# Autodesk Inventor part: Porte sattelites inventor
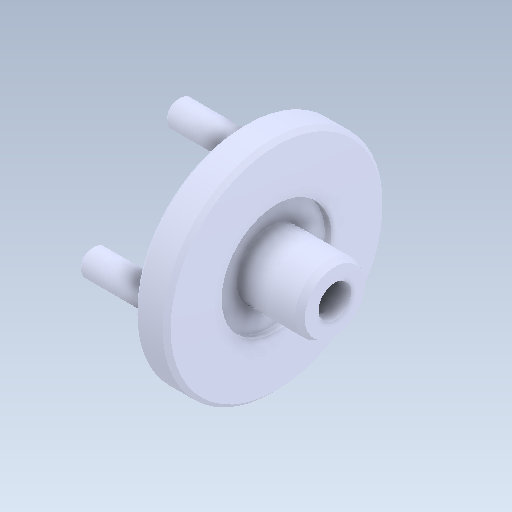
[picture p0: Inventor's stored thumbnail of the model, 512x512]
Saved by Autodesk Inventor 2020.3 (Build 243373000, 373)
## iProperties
Created: 2019-01
Part Number: Porte sattelites inventor
Material: Générique
Document SubType Name: Modeling
Designer: ficho
Density: 1 g/cm^3
Appearance: Par défaut
Mass: 0.619253 g
Surface Area: 7.99302 cm^2
Volume: 0.619253 cm^3
Sending System: SolidWorks 2015
Last Author: adrien
Last Saved: 2019-01-11
Author: ficho
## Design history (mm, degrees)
node "Boss.-Extru.3"
sketch "Esquisse1"
  geometry: A1 r 2.909 centre (0.384, 3.431) between (-2.245, 2.184) and (-1.899, 1.627) reference; A2 r 2.5 centre (0, 0) between (-0.96, 2.308) and (-1.899, 1.627) reference; A3 r 2.909 centre (-3.381, 0.695) between (-0.96, 2.308) and (-1.383, 2.81) reference; A4 r 4.512 centre (-3.768, -1.02) between (-1.383, 2.81) and (-2.039, 3.147) reference; A5 r 3.75 centre (0, 0) between (-2.039, 3.147) and (-2.363, 2.912) reference; A6 r 4.512 centre (2.135, 3.268) between (-2.363, 2.912) and (-2.245, 2.184) reference; A7 r 2.909 centre (-1.706, 3.001) between (-3.1, 0.447) and (-2.492, 0.2) reference; A8 r 2.5 centre (0, 0) between (-2.134, 1.303) and (-2.492, 0.2) reference; A9 r 2.909 centre (-3.144, -1.425) between (-2.134, 1.303) and (-2.771, 1.46) reference; A10 r 4.512 centre (-2.448, -3.04) between (-2.771, 1.46) and (-3.5, 1.347) reference; A11 r 3.75 centre (0, 0) between (-3.5, 1.347) and (-3.623, 0.967) reference; A12 r 4.512 centre (-0.194, 3.899) between (-3.623, 0.967) and (-3.1, 0.447) reference; A13 r 2.909 centre (-3.144, 1.425) between (-2.771, -1.46) and (-2.134, -1.303) reference; A14 r 2.5 centre (0, 0) between (-2.492, -0.2) and (-2.134, -1.303) reference; A15 r 2.909 centre (-1.706, -3.001) between (-2.492, -0.2) and (-3.1, -0.447) reference; A16 r 4.512 centre (-0.194, -3.899) between (-3.1, -0.447) and (-3.623, -0.967) reference; A17 r 3.75 centre (0, 0) between (-3.623, -0.967) and (-3.5, -1.347) reference; A18 r 4.512 centre (-2.448, 3.04) between (-3.5, -1.347) and (-2.771, -1.46) reference; A19 r 2.909 centre (-3.381, -0.695) between (-1.383, -2.81) and (-0.96, -2.308) reference; A20 r 2.5 centre (0, 0) between (-1.899, -1.627) and (-0.96, -2.308) reference; A21 r 2.909 centre (0.384, -3.431) between (-1.899, -1.627) and (-2.245, -2.184) reference; A22 r 4.512 centre (2.135, -3.268) between (-2.245, -2.184) and (-2.363, -2.912) reference; A23 r 3.75 centre (0, 0) between (-2.363, -2.912) and (-2.039, -3.147) reference; A24 r 4.512 centre (-3.768, 1.02) between (-2.039, -3.147) and (-1.383, -2.81) reference; A25 r 2.909 centre (-2.327, -2.55) between (0.532, -3.086) and (0.58, -2.432) reference; A26 r 2.5 centre (0, 0) between (-0.58, -2.432) and (0.58, -2.432) reference; A27 r 2.909 centre (2.327, -2.55) between (-0.58, -2.432) and (-0.532, -3.086) reference; A28 r 4.512 centre (3.648, -1.389) between (-0.532, -3.086) and (-0.2, -3.745) reference; A29 r 3.75 centre (0, 0) between (-0.2, -3.745) and (0.2, -3.745) reference; A30 r 4.512 centre (-3.648, -1.389) between (0.2, -3.745) and (0.532, -3.086) reference; A31 r 2.909 centre (-0.384, -3.431) between (2.245, -2.184) and (1.899, -1.627) reference; A32 r 2.5 centre (0, 0) between (0.96, -2.308) and (1.899, -1.627) reference; A33 r 2.909 centre (3.381, -0.695) between (0.96, -2.308) and (1.383, -2.81) reference; A34 r 4.512 centre (3.768, 1.02) between (1.383, -2.81) and (2.039, -3.147) reference; A35 r 3.75 centre (0, 0) between (2.039, -3.147) and (2.363, -2.912) reference; A36 r 4.512 centre (-2.135, -3.268) between (2.363, -2.912) and (2.245, -2.184) reference; A37 r 2.909 centre (1.706, -3.001) between (3.1, -0.447) and (2.492, -0.2) reference; A38 r 2.5 centre (0, 0) between (2.134, -1.303) and (2.492, -0.2) reference; A39 r 2.909 centre (3.144, 1.425) between (2.134, -1.303) and (2.771, -1.46) reference; A40 r 4.512 centre (2.448, 3.04) between (2.771, -1.46) and (3.5, -1.347) reference; A41 r 3.75 centre (0, 0) between (3.5, -1.347) and (3.623, -0.967) reference; A42 r 4.512 centre (0.194, -3.899) between (3.623, -0.967) and (3.1, -0.447) reference; A43 r 2.909 centre (3.144, -1.425) between (2.771, 1.46) and (2.134, 1.303) reference; A44 r 2.5 centre (0, 0) between (2.492, 0.2) and (2.134, 1.303) reference; A45 r 2.909 centre (1.706, 3.001) between (2.492, 0.2) and (3.1, 0.447) reference; A46 r 4.512 centre (0.194, 3.899) between (3.1, 0.447) and (3.623, 0.967) reference; A47 r 3.75 centre (0, 0) between (3.623, 0.967) and (3.5, 1.347) reference; A48 r 4.512 centre (2.448, -3.04) between (3.5, 1.347) and (2.771, 1.46) reference; A49 r 2.909 centre (3.381, 0.695) between (1.383, 2.81) and (0.96, 2.308) reference; A50 r 2.5 centre (0, 0) between (1.899, 1.627) and (0.96, 2.308) reference; A51 r 2.909 centre (-0.384, 3.431) between (1.899, 1.627) and (2.245, 2.184) reference; A52 r 4.512 centre (-2.135, 3.268) between (2.245, 2.184) and (2.363, 2.912) reference; A53 r 3.75 centre (0, 0) between (2.363, 2.912) and (2.039, 3.147) reference; A54 r 4.512 centre (3.768, -1.02) between (2.039, 3.147) and (1.383, 2.81) reference; A55 r 2.909 centre (2.327, 2.55) between (-0.532, 3.086) and (-0.58, 2.432) reference; A56 r 2.5 centre (0, 0) between (0.58, 2.432) and (-0.58, 2.432) reference; A57 r 2.909 centre (-2.327, 2.55) between (0.58, 2.432) and (0.532, 3.086) reference; A58 r 4.512 centre (-3.648, 1.389) between (0.532, 3.086) and (0.2, 3.745) reference; A59 r 3.75 centre (0, 0) between (0.2, 3.745) and (-0.2, 3.745) reference; A60 r 4.512 centre (3.648, 1.389) between (-0.2, 3.745) and (-0.532, 3.086) reference; 1 further point
extrude "Extrusion1" cut sketch "Esquisse1" extent not by distance; stored distance "d0" = 4.9; taper "d1" = 0 deg
sketch "Esquisse2"
  geometry: C1 r 8.3 at (0, 0) reference; C2 r 1 at (0, 0) reference; 1 further point
extrude "Extrusion2" cut sketch "Esquisse2" extent not by distance; stored distance "d2" = 4; taper "d3" = 0 deg
sketch "Esquisse3"
  geometry: C1 r 1 at (0, 6.5); 1 further point
  constraints: 1 centre point
  dimensions: "d4" = 2 diameter of C1; "d5" = 6.5 distance of C1.centre point (0, 0)
extrude "Extrusion3" join sketch "Esquisse3" distance "d6" = 5; taper "d7" = 0 deg
chamfer "Chanfrein1" distance "d8" = 0.25; stored, may be unused: second distance "d9" = 2, angle "d10" = 45 deg
pattern_circular "Réseau circulaire1" dims angle "d12" = 360 deg
node "Solide1"
node "Boucle projetée1"
node "Boucle projetée2"
node "Boucle projetée3"
node "Boucle projetée4"
node "Boucle projetée5"
node "Boucle projetée6"
node "Boucle projetée7"
node "Boucle projetée8"
node "Boucle projetée9"
node "Boucle projetée10"
